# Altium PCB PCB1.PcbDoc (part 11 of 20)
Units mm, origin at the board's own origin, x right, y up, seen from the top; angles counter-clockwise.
Board outline 294.51 x 138.18 mm, 12 copper layers (Top Layer 1 _Signal, L2_GND, L3_Signals, L4_GND, L5_POWER, L6_Signals, L7_GND, L8_Signals, L9_GND, L10_POWER, L11_GND, Bottom Layer_Signals), stack 1.788 mm thick; 1254 components, 836 nets, 5699 pads, 2073 vias.
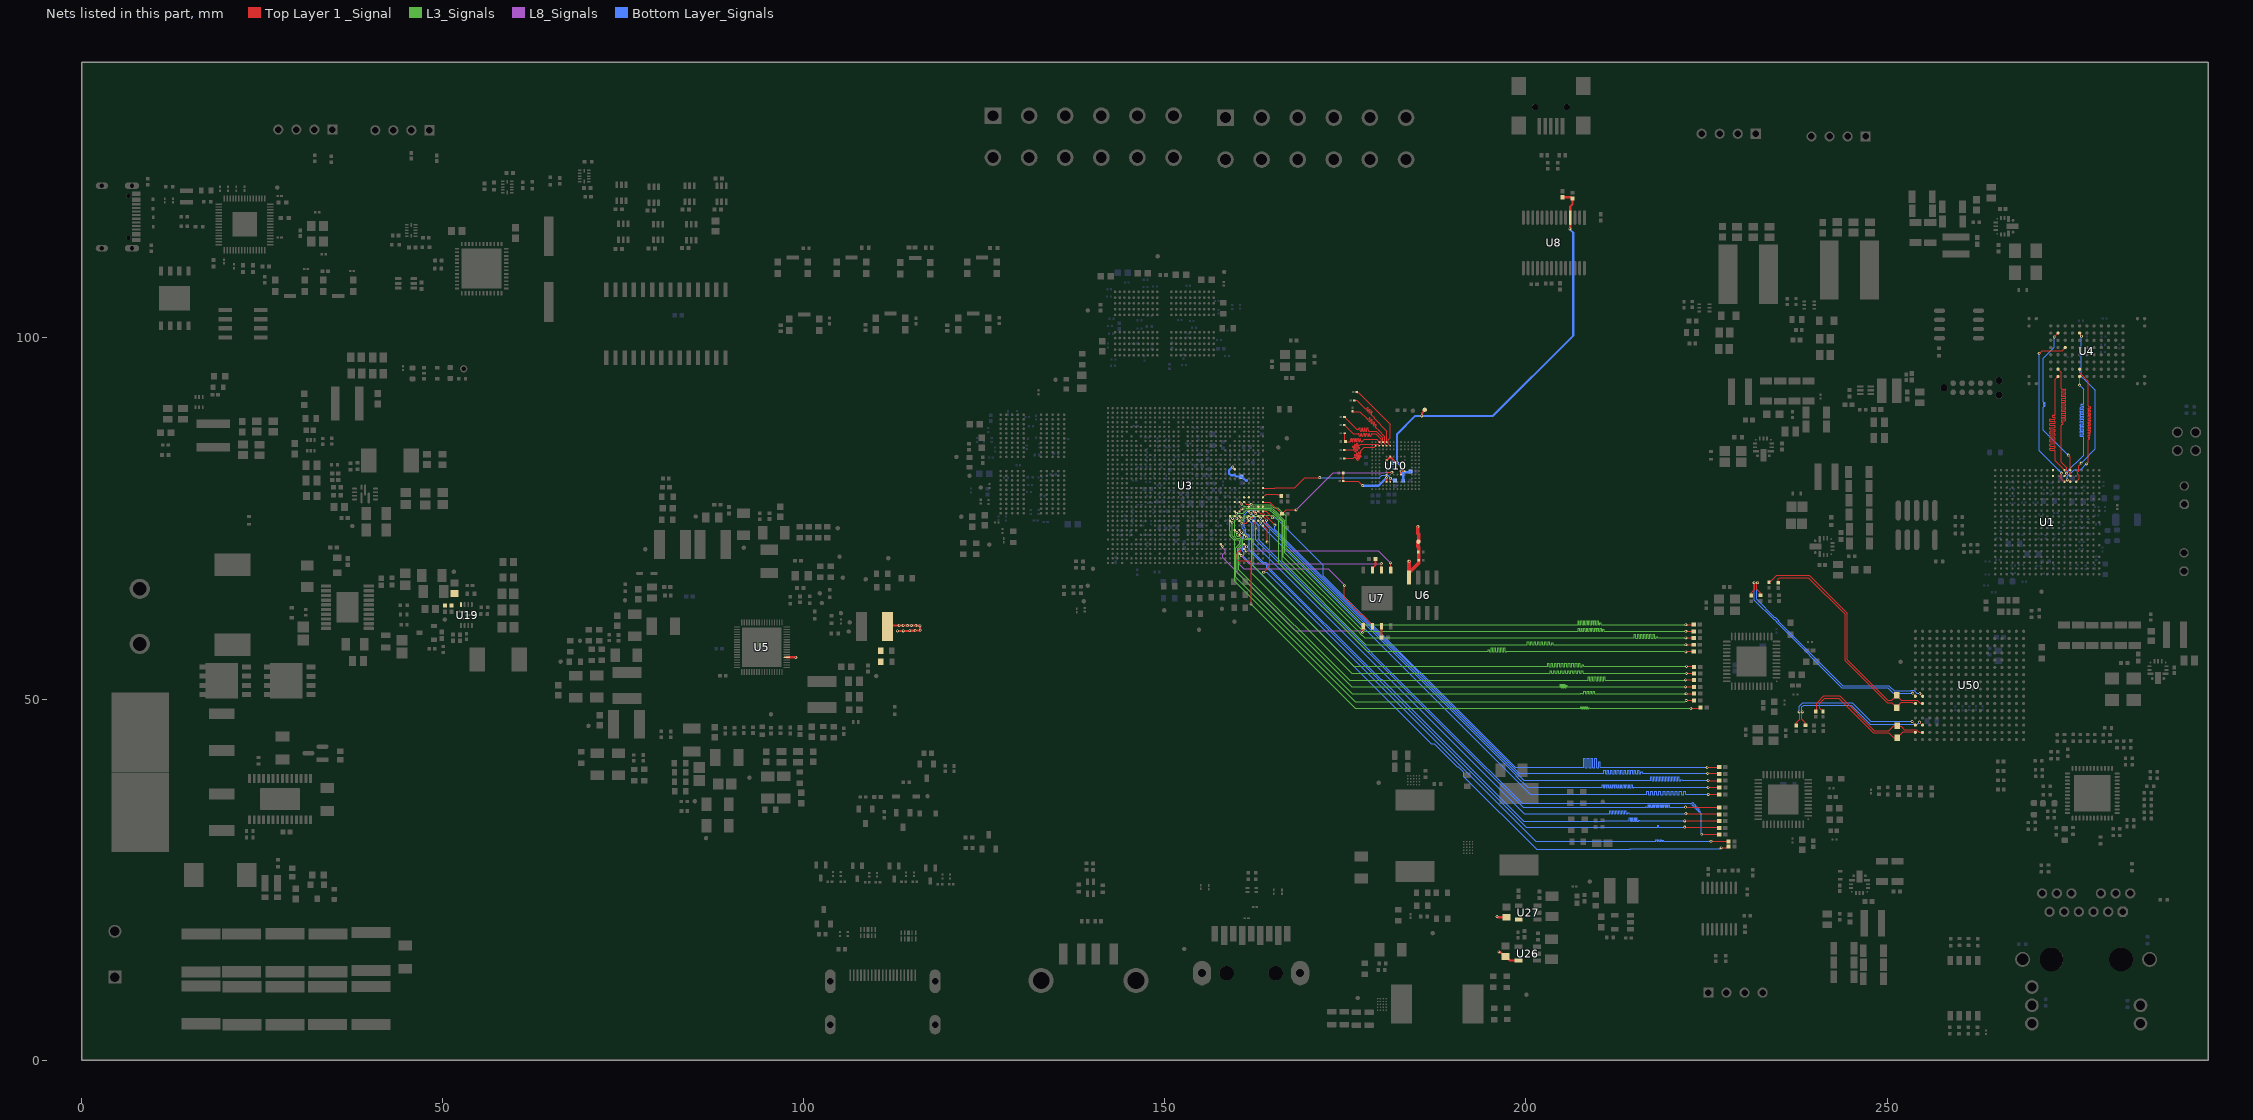
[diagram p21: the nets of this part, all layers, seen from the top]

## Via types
v1: diameter 0.4, hole 0.2, Top Layer 1 _Signal to Bottom Layer_Signals, 2009 vias
v2: diameter 0.508, hole 0.254, Top Layer 1 _Signal to Bottom Layer_Signals, 36 vias
v3: diameter 0.5, hole 0.2, Top Layer 1 _Signal to Bottom Layer_Signals, 12 vias
v4: diameter 1.27, hole 0.711, Top Layer 1 _Signal to Bottom Layer_Signals, 6 vias
v5: diameter 0.3, hole 0.2, Top Layer 1 _Signal to Bottom Layer_Signals, 5 vias
v6: diameter 0.254, hole 0.2, Top Layer 1 _Signal to Bottom Layer_Signals, 3 vias
v7: diameter 0.305, hole 0.2, Top Layer 1 _Signal to Bottom Layer_Signals, 1 vias
v8: diameter 0.254, hole 0.152, Top Layer 1 _Signal to Bottom Layer_Signals, 1 vias

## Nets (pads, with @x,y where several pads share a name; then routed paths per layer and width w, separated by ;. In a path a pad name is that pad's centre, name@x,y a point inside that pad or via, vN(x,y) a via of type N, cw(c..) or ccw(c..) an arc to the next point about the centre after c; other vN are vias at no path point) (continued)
EMMC.D2: U1.E3 U4.K3 | length 22.7
  Top Layer 1 _Signal w0.132: U1.E3@276.181,80.08 276.584,80.483 276.584,80.966 276.398,81.151 276.398,81.441 276.528,81.571 276.528,82.329 v1(276.867,82.668) ; U4.K3@276.672,100.669 276.672,100.583 276.925,100.329 v1(276.925,100.226)
  Bottom Layer_Signals w0.132: v1(276.867,82.668) 278.827,84.628 278.827,92.78 277.403,94.204 277.376,94.204 276.925,94.655 v1(276.925,100.226)
EMMC.D3: U1.F1 U4.N3 | length 22.2
  Top Layer 1 _Signal w0.132: v1(273.158,100.13) 273.158,100.155 U4.N3@273.672,100.669 ; v1(275.089,83.765) 275.343,83.511 275.343,81.718 U1.F1@275.381,81.68
  Bottom Layer_Signals w0.132: v1(273.158,100.13) 273.158,98.696 271.63,97.168 271.63,92.119 271.63,91.156 ccw(c271.762,91.156) 271.762,91.024 271.825,91.024 cw(c271.825,90.945) 271.825,90.867 271.683,90.867 ccw(c271.683,90.788) 271.683,90.709 271.825,90.709 cw(c271.825,90.631) 271.825,90.552 271.762,90.552 ccw(c271.762,90.42) 271.63,90.42 271.63,90.197 271.63,87.224 v1(275.089,83.765)
EMMC.D4: U1.F2 U4.N8 | length 26
  Top Layer 1 _Signal w0.132: U4.N8@273.672,95.669 274.122,95.218 274.122,93.123 274.122,93.058 ccw(c274.254,93.058) 274.254,92.926 274.646,92.926 cw(c274.646,92.796) 274.646,92.667 274.226,92.667 ccw(c274.226,92.537) 274.226,92.408 274.646,92.408 cw(c274.646,92.279) 274.646,92.149 274.226,92.149 ccw(c274.226,92.02) 274.226,91.89 274.646,91.89 cw(c274.646,91.761) 274.646,91.632 274.226,91.632 ccw(c274.226,91.502) 274.226,91.373 274.646,91.373 cw(c274.646,91.243) 274.646,91.114 274.226,91.114 ccw(c274.226,90.985) 274.226,90.855 274.646,90.855 cw(c274.646,90.726) 274.646,90.596 274.226,90.596 ccw(c274.226,90.467) 274.226,90.337 274.646,90.337 cw(c274.646,90.208) 274.646,90.079 274.226,90.079 ccw(c274.226,89.949) 274.226,89.82 274.646,89.82 cw(c274.646,89.69) 274.646,89.561 274.226,89.561 ccw(c274.226,89.432) 274.226,89.302 274.646,89.302 cw(c274.646,89.173) 274.646,89.043 274.226,89.043 ccw(c274.226,88.914) 274.226,88.785 274.617,88.785 cw(c274.617,88.655) 274.617,88.526 274.226,88.526 ccw(c274.226,88.396) 274.226,88.267 274.254,88.267 cw(c274.254,88.137) 274.254,88.008 ccw(c274.254,87.876) 274.122,87.876 274.122,87.563 274.122,82.786 274.917,81.991 274.917,81.699 275.373,81.243 275.373,80.888 U1.F2@275.381,80.88
EMMC.D5: U1.F3 U4.K8 | length 23.4
  Top Layer 1 _Signal w0.132: v1(274.955,80.34) 275.006,80.289 275.118,80.289 275.327,80.08 U1.F3@275.381,80.08 ; U4.K8@276.672,95.669 276.672,95.166 276.794,95.043 276.827,95.043 277.297,94.573 277.297,94.513 277.831,93.979 277.831,90.656 277.831,90.59 ccw(c277.963,90.59) 277.963,90.459 278.076,90.459 cw(c278.076,90.342) 278.076,90.225 277.923,90.225 ccw(c277.923,90.108) 277.923,89.992 278.076,89.992 cw(c278.076,89.875) 278.076,89.758 277.923,89.758 ccw(c277.923,89.642) 277.923,89.525 278.076,89.525 cw(c278.076,89.408) 278.076,89.291 277.923,89.291 ccw(c277.923,89.175) 277.923,89.058 278.076,89.058 cw(c278.076,88.941) 278.076,88.825 277.923,88.825 ccw(c277.923,88.708) 277.923,88.591 278.076,88.591 cw(c278.076,88.474) 278.076,88.358 277.923,88.358 ccw(c277.923,88.241) 277.923,88.124 278.076,88.124 cw(c278.076,88.008) 278.076,87.891 277.923,87.891 ccw(c277.923,87.774) 277.923,87.658 278.076,87.658 cw(c278.076,87.541) 278.076,87.424 277.923,87.424 ccw(c277.923,87.307) 277.923,87.191 278.076,87.191 cw(c278.076,87.074) 278.076,86.957 277.923,86.957 ccw(c277.923,86.841) 277.923,86.724 278.003,86.724 cw(c278.003,86.607) 278.003,86.49 277.923,86.49 ccw(c277.923,86.374) 277.923,86.257 277.963,86.257 cw(c277.963,86.14) 277.963,86.024 ccw(c277.963,85.892) 277.831,85.892 277.831,85.537 277.831,82.775 v1(277.61,82.554)
  Bottom Layer_Signals w0.132: v1(274.955,80.34) 274.985,80.371 274.985,80.828 275.928,81.77 276.827,81.77 v1(277.61,82.554)
EMMC.D6: U1.G1 U4.N9 | length 25.4
  Top Layer 1 _Signal w0.132: U4.N9@273.672,94.669 273.274,94.271 273.274,89.798 273.274,89.441 cw(c273.132,89.441) 273.132,89.299 273.015,89.299 ccw(c273.015,89.157) 273.015,89.015 273.158,89.015 cw(c273.158,88.872) 273.158,88.73 272.626,88.73 ccw(c272.626,88.588) 272.626,88.446 273.158,88.446 cw(c273.158,88.304) 273.158,88.162 272.626,88.162 ccw(c272.626,88.02) 272.626,87.878 273.158,87.878 cw(c273.158,87.736) 273.158,87.593 272.626,87.593 ccw(c272.626,87.451) 272.626,87.309 273.158,87.309 cw(c273.158,87.167) 273.158,87.025 272.626,87.025 ccw(c272.626,86.883) 272.626,86.741 273.158,86.741 cw(c273.158,86.599) 273.158,86.457 272.626,86.457 ccw(c272.626,86.314) 272.626,86.172 273.158,86.172 cw(c273.158,86.03) 273.158,85.888 272.626,85.888 ccw(c272.626,85.746) 272.626,85.604 273.158,85.604 cw(c273.158,85.462) 273.158,85.32 272.626,85.32 ccw(c272.626,85.177) 272.626,85.035 273.158,85.035 cw(c273.158,84.893) 273.158,84.751 272.626,84.751 ccw(c272.626,84.609) 272.626,84.467 273.132,84.467 cw(c273.132,84.325) 273.274,84.325 273.274,84.259 273.274,82.987 U1.G1@274.581,81.68
EMMC.D7: U1.G2 U4.K9 | length 23.6
  Top Layer 1 _Signal w0.132: U1.G2@274.581,80.88 274.865,81.164 v1(274.865,81.256) ; v1(276.663,93.461) 276.667,93.466 276.667,94.665 U4.K9@276.672,94.669
  Bottom Layer_Signals w0.132: v1(274.865,81.256) 274.916,81.308 274.916,81.47 277.216,83.77 277.216,86.174 277.216,86.239 ccw(c277.084,86.239) 277.084,86.371 276.816,86.371 cw(c276.816,86.488) 276.816,86.605 277.124,86.605 ccw(c277.124,86.721) 277.124,86.838 276.816,86.838 cw(c276.816,86.955) 276.816,87.072 277.124,87.072 ccw(c277.124,87.188) 277.124,87.305 276.816,87.305 cw(c276.816,87.422) 276.816,87.538 277.124,87.538 ccw(c277.124,87.655) 277.124,87.772 276.816,87.772 cw(c276.816,87.889) 276.816,88.005 277.124,88.005 ccw(c277.124,88.122) 277.124,88.239 276.816,88.239 cw(c276.816,88.355) 276.816,88.472 277.124,88.472 ccw(c277.124,88.589) 277.124,88.706 276.816,88.706 cw(c276.816,88.822) 276.816,88.939 277.124,88.939 ccw(c277.124,89.056) 277.124,89.172 276.816,89.172 cw(c276.816,89.289) 276.816,89.406 277.124,89.406 ccw(c277.124,89.523) 277.124,89.639 276.816,89.639 cw(c276.816,89.756) 276.816,89.873 277.124,89.873 ccw(c277.124,89.989) 277.124,90.106 276.816,90.106 cw(c276.816,90.223) 276.816,90.34 277.124,90.34 ccw(c277.124,90.456) 277.124,90.573 276.934,90.573 cw(c276.934,90.69) 276.934,90.806 277.084,90.806 ccw(c277.084,90.938) 277.216,90.938 277.216,91.818 277.216,92.909 v1(276.663,93.461)
EMMC.RSTn: U1.G3 U4.M5 | length 23.2
  Top Layer 1 _Signal w0.132: v1(271.06,97.818) 271.48,98.239 274.241,98.239 U4.M5@274.672,98.669 ; v1(274.162,81.282) 274.126,81.245 274.126,80.535 U1.G3@274.581,80.08
  Bottom Layer_Signals w0.132: v1(271.06,97.818) 271.06,84.384 v1(274.162,81.282)
EMMC_CLK: C217.2 U3.V34 U10.M6 | length 19.9
  Top Layer 1 _Signal w0.132: U3.V34@163.579,79.228 163.615,79.192 163.769,79.192 163.779,79.182 165.242,79.182 165.303,79.243 167.992,79.243 169.399,80.649 v1(171.44,80.649) ; U10.M6@181.204,80.07 181.214,80.08 181.214,80.555 v1(181.224,80.565)
  Bottom Layer_Signals w0.132: v1(171.44,80.649) 179.694,80.649 180.049,81.004 180.841,81.004 181.046,80.799 181.046,80.777 181.224,80.599 v1(181.224,80.565) ; v1@181.292,80.565 181.483,80.374 181.73,80.374 C217.2@181.87,80.235
eMMC_CMD: R60.1 R67.2 U10.M5 | length 8.4
  Top Layer 1 _Signal w0.132: R67.2@174.714,81.322 174.723,81.313 174.723,80.185 R60.1@174.731,80.176 176.767,80.176 v1(177.402,79.542)
  Top Layer 1 _Signal w0.305: v1(180.697,80.654) 180.697,80.629 180.704,80.623 U10.M5@180.704,80.07
  Bottom Layer_Signals w0.305: v1(177.402,79.542) 179.584,79.542 v1(180.697,80.654)
EMMC_D0: R56.1 R65.2 U10.A3 | length 9.6
  Top Layer 1 _Signal w0.132: R56.1@174.882,86.796 174.882,85.796 175.014,85.664 R65.2@175.014,85.639 175.531,85.639 175.597,85.639 ccw(c175.597,85.771) 175.728,85.771 175.728,85.99 cw(c175.807,85.99) 175.886,85.99 175.886,85.717 ccw(c175.964,85.717) 176.043,85.717 176.043,85.99 cw(c176.122,85.99) 176.2,85.99 176.2,85.717 ccw(c176.279,85.717) 176.357,85.717 176.357,85.99 cw(c176.436,85.99) 176.515,85.99 176.515,85.717 ccw(c176.593,85.717) 176.672,85.717 176.672,85.99 cw(c176.75,85.99) 176.829,85.99 176.829,85.717 ccw(c176.908,85.717) 176.986,85.717 176.986,85.906 cw(c177.065,85.906) 177.143,85.906 177.143,85.771 ccw(c177.275,85.771) 177.275,85.639 177.317,85.639 177.623,85.945 177.631,85.953 179.32,85.953 U10.A3@179.704,85.57
EMMC_D1: R57.1 U10.A4 | length 9.6
  Top Layer 1 _Signal w0.132: R57.1@174.876,89.049 174.922,89.049 176.534,87.437 176.6,87.371 176.607,87.364 ccw(c176.717,87.475) 176.864,87.423 cw(c176.955,87.423) 177.046,87.423 177.046,87.164 ccw(c177.138,87.164) 177.229,87.164 177.229,87.423 cw(c177.32,87.423) 177.412,87.423 177.412,87.164 ccw(c177.503,87.164) 177.594,87.164 177.594,87.423 cw(c177.686,87.423) 177.777,87.423 177.777,87.164 ccw(c177.868,87.164) 177.959,87.164 177.959,87.423 cw(c178.051,87.423) 178.142,87.423 178.142,87.23 ccw(c178.274,87.23) 178.274,87.098 178.663,87.098 179.253,87.098 180.204,86.147 U10.A4@180.204,85.57
EMMC_D2: R58.1 U10.A5 | length 9.7
  Top Layer 1 _Signal w0.132: R58.1@176.23,91.348 176.604,91.348 177.697,90.256 177.744,90.209 ccw(c177.837,90.302) 177.93,90.209 178.041,90.32 cw(c178.106,90.256) 178.17,90.32 cw(c178.106,90.256) 178.17,90.191 178.013,90.033 ccw(c178.077,89.969) 178.013,89.904 ccw(c178.077,89.969) 178.142,89.904 178.299,90.062 cw(c178.364,89.997) 178.429,90.062 cw(c178.364,89.997) 178.429,89.933 178.271,89.775 ccw(c178.336,89.711) 178.271,89.646 ccw(c178.336,89.711) 178.4,89.646 178.552,89.798 cw(c178.617,89.734) 178.682,89.798 cw(c178.617,89.734) 178.682,89.669 178.576,89.564 ccw(c178.669,89.47) 178.576,89.377 178.962,88.991 178.962,88.865 178.962,88.856 180.726,87.091 180.726,85.592 U10.A5@180.704,85.57
eMMC_D3: R59.1 U10.B2 | length 9.8
  Top Layer 1 _Signal w0.089: 178.421,84.836 178.97,84.836
  Top Layer 1 _Signal w0.132: R59.1@174.851,83.315 175.728,83.315 176.087,83.315 176.158,83.387 cw(c176.252,83.294) 176.345,83.387 176.642,83.09 ccw(c176.698,83.145) 176.753,83.09 ccw(c176.698,83.145) 176.753,83.201 176.247,83.707 cw(c176.303,83.762) 176.247,83.818 cw(c176.303,83.762) 176.359,83.818 176.865,83.312 ccw(c176.92,83.368) 176.976,83.312 ccw(c176.92,83.368) 176.976,83.423 176.519,83.88 cw(c176.575,83.935) 176.519,83.991 cw(c176.575,83.935) 176.63,83.991 177.087,83.534 ccw(c177.142,83.59) 177.198,83.534 ccw(c177.142,83.59) 177.198,83.646 176.777,84.067 cw(c176.832,84.122) 176.777,84.178 cw(c176.832,84.122) 176.888,84.178 177.012,84.054 ccw(c177.067,84.11) 177.123,84.054 ccw(c177.067,84.11) 177.123,84.165 cw(c177.216,84.259) 177.123,84.352 177.284,84.513 177.608,84.836 178.421,84.836 ; 178.97,84.836 U10.B2@179.204,85.07
eMMC_D4: R62.1 U10.B3 | length 9.8
  Top Layer 1 _Signal w0.089: 178.439,85.285 178.466,85.311 179.462,85.311
  Top Layer 1 _Signal w0.132: R62.1@174.849,84.489 175.46,84.489 176.093,84.489 cw(c176.093,84.357) 176.187,84.451 176.38,84.257 ccw(c176.436,84.313) 176.491,84.257 ccw(c176.436,84.313) 176.491,84.368 176.003,84.857 cw(c176.058,84.913) 176.003,84.968 cw(c176.058,84.913) 176.114,84.968 176.603,84.48 ccw(c176.658,84.535) 176.714,84.48 ccw(c176.658,84.535) 176.714,84.591 176.225,85.079 cw(c176.281,85.135) 176.225,85.191 cw(c176.281,85.135) 176.336,85.191 176.825,84.702 ccw(c176.88,84.757) 176.936,84.702 ccw(c176.88,84.757) 176.936,84.813 176.523,85.227 cw(c176.578,85.282) 176.523,85.338 cw(c176.578,85.282) 176.634,85.338 176.802,85.17 ccw(c176.895,85.263) 176.988,85.17 177.104,85.285 177.173,85.285 178.439,85.285 ; 179.462,85.311 U10.B3@179.704,85.07
eMMC_D5: R63.1 U10.B4 | length 9.6
  Top Layer 1 _Signal w0.089: 179.955,85.319 179.955,85.961
  Top Layer 1 _Signal w0.132: R63.1@174.87,87.923 174.916,87.923 176.109,86.729 176.546,86.729 176.795,86.729 cw(c176.795,86.597) 176.927,86.597 176.927,86.489 ccw(c177.018,86.489) 177.109,86.489 177.109,86.663 cw(c177.201,86.663) 177.292,86.663 177.292,86.489 ccw(c177.383,86.489) 177.475,86.489 177.475,86.663 cw(c177.566,86.663) 177.657,86.663 177.657,86.489 ccw(c177.749,86.489) 177.84,86.489 177.84,86.663 cw(c177.931,86.663) 178.023,86.663 178.023,86.489 ccw(c178.114,86.489) 178.205,86.489 178.205,86.663 cw(c178.296,86.663) 178.388,86.663 178.388,86.489 ccw(c178.479,86.489) 178.57,86.489 178.57,86.597 cw(c178.702,86.597) 178.702,86.729 179.187,86.729 179.263,86.653 179.955,85.961 ; 179.955,85.319 U10.B4@180.204,85.07
eMMC_D6: R61.1 U10.B5 | length 9.6
  Top Layer 1 _Signal w0.089: 180.445,85.329 180.445,86.336
  Top Layer 1 _Signal w0.132: R61.1@175.985,89.832 176.003,89.832 176.05,89.785 176.996,89.785 177.931,88.85 177.977,88.803 ccw(c178.071,88.896) 178.164,88.803 178.272,88.911 cw(c178.346,88.838) 178.419,88.911 cw(c178.346,88.838) 178.419,88.764 178.273,88.618 ccw(c178.347,88.545) 178.273,88.471 ccw(c178.347,88.545) 178.42,88.471 178.566,88.617 cw(c178.64,88.544) 178.713,88.617 cw(c178.64,88.544) 178.713,88.47 178.568,88.324 ccw(c178.641,88.251) 178.568,88.177 ccw(c178.641,88.251) 178.715,88.177 178.86,88.323 cw(c178.934,88.249) 179.008,88.323 cw(c178.934,88.249) 179.008,88.176 178.862,88.03 ccw(c178.935,87.956) 178.862,87.883 ccw(c178.935,87.956) 179.009,87.883 179.086,87.96 cw(c179.159,87.886) 179.233,87.96 cw(c179.159,87.886) 179.233,87.813 179.194,87.773 ccw(c179.287,87.68) 179.194,87.587 179.522,87.259 180.445,86.336 ; 180.445,85.329 U10.B5@180.704,85.07
eMMC_D7: R64.1 U10.B6 | length 9.7
  Top Layer 1 _Signal w0.089: 180.945,85.329 180.945,85.925
  Top Layer 1 _Signal w0.132: R64.1@176.578,92.5 176.644,92.434 176.815,92.434 181.222,88.027 181.222,86.202 180.945,85.925 ; 180.945,85.329 U10.B6@181.204,85.07
eMMC_DATA_STROBE: R68.2 U3.Y34 | length 2.8
  Top Layer 1 _Signal w0.132: U3.Y34@163.579,77.928 164.014,78.362 164.26,78.362 164.277,78.379 164.566,78.379 164.588,78.357 165.531,78.357 165.617,78.272 165.978,78.272 R68.2@166.13,78.119
eMMC_RSTn: R66.1 U3.AA34 U10.K5 | length 21.9
  Top Layer 1 _Signal w0.132: U3.AA34@163.579,77.278 164.554,77.278 R66.1@166.179,75.652 ; R66.1@166.223,75.652 R66.1@166.179,75.652 ; v1(168.186,76.182) 166.778,76.182 166.546,75.95 166.546,75.932 166.266,75.652 R66.1@166.179,75.652 ; U10.K5@180.704,81.07 181.016,81.382 181.409,81.382 v1(181.434,81.407) v1@181.423,81.419
  L8_Signals w0.089: v1(168.186,76.182) 173.305,81.302 180.382,81.302 180.487,81.407 v1(181.434,81.407)
EMMC_VCC: C23.1 C73.1 C74.1 C207.2 C208.2 C209.1 C520.2 C521.2 C543.1 C544.2 L10.1 R122.2 R301.2 R304.2 TP22.1 TP42.1 U3.P28 U5.5 U6.8 U8.4 U10.E6 U10.F5 U10.J10 U10.K9 U26.5 U27.5 | length 91.6
  Top Layer 1 _Signal w0.305: U5.5@97.644,55.77 v1(98.913,55.77) ; L10.1@111.572,60.058 111.698,60.184 v1(113.2,60.184) v1(113.753,60.184) 113.758,60.179 114.349,60.179 v1(114.354,60.175) 114.358,60.179 114.902,60.179 v1(114.907,60.184) 114.916,60.175 115.516,60.175 v1(115.526,60.165) 115.54,60.151 116.084,60.151 v1(116.098,60.137) 116.112,60.123 116.112,59.532 v1(116.126,59.518) 116.1,59.518 116.053,59.471 v1(115.423,59.471) 115.413,59.462 114.682,59.462 v1(114.672,59.453) 114.658,59.439 113.796,59.439 v1(113.782,59.425) 113.777,59.429 112.98,59.429 v1(112.975,59.434) ; v1(159.406,82.126) 159.406,82.119 159.419,82.106 159.419,82.092 159.679,81.832 U3.P28@159.679,81.828 U3.P28@159.675,81.828 ; U10.F5@180.704,83.07 180.714,83.07 181.204,83.559 U10.E6@181.204,83.57 181.342,83.431 181.342,83.42 182.028,82.735 v1(182.142,82.735) ; U10.K9@182.704,81.07 182.704,81.55 v1(182.717,81.563) 182.724,81.57 U10.J10@183.204,81.57 ; v1(185.578,89.206) 185.596,89.225 185.596,89.577 185.985,89.966 TP42.1@185.985,90.045 ; v1(195.988,19.884) 196.1,19.772 C521.2@197.29,19.772 ; v1(196.25,14.986) 196.268,14.968 196.457,14.968 197.082,14.343 C520.2@197.157,14.343 197.232,14.343 197.784,13.791 U26.5@198.953,13.791 ; C544.2@205.073,119.486 206.244,119.486 C543.1@206.43,119.3 206.43,118.485 206.141,118.196 U8.4@206.141,116.664 206.141,115.187 206.085,115.131 v1(206.085,115.105)
  Top Layer 1 _Signal w0.508: U6.8@183.795,66.832 U6.8@183.795,67.482 ; v1(183.83,69.081) 183.795,69.046 U6.8@183.795,67.482 ; v1(185.033,73.871) 185.038,73.867 185.038,72.942 185.055,72.924 185.055,72.899 185.177,72.778 185.177,71.881 185.111,71.815 TP22.1@185.111,71.79 ; TP22.1@185.055,71.79 185.055,71.107 185.157,71.006 R301.2@185.157,69.214 185.157,68.844 U6.8@183.795,67.482
  Bottom Layer_Signals w0.254: R122.2@160.557,80.827 160.557,80.802 160.911,80.449 160.959,80.449 161.153,80.254 161.348,80.254 C23.1@161.352,80.25
  Bottom Layer_Signals w0.305: v1(159.406,82.126) 159.38,82.126 159.217,81.962 159.174,81.962 158.918,81.706 158.918,81.644 158.881,81.607 158.881,81.236 159.138,80.979 159.712,80.979 159.864,80.827 160.557,80.827 R122.2@160.596,80.788 ; C207.2@181.506,82.761 v1@182.142,82.761 ; v1(182.142,82.735) v1@182.142,82.761 ; 182.874,81.38 183.012,81.241 183.012,80.309 183.019,80.302 C209.1@183.019,80.211 ; C208.2@184.028,81.494 183.94,81.406 182.9,81.406 182.742,81.563 v1(182.717,81.563) 182.717,82.255 182.21,82.761 v1@182.142,82.761 ; v1(206.085,115.105) 206.085,115.038 206.552,114.571 206.552,100.322 195.436,89.206 v1(185.578,89.206) 184.667,89.206 182.142,86.682 v1@182.142,82.761
EN_MP: C201.2 R81.1 R86.2 U19.12
FC1.RXD: U1.J1
FC1.TXD: U1.J2
FIBRI0_N: R228.1 R260.1 U50.T15 | length 17.5
  Top Layer 1 _Signal w0.161: R228.1@241.136,48.275 241.136,48.3 240.697,48.739 240.697,49.431 240.789,49.523 241.371,50.105 243.309,50.105 248.108,45.306 250.238,45.306 250.931,44.613 R260.1@251.412,44.613 252.247,45.448 253.687,45.448 253.703,45.432 253.866,45.432 U50.T15@253.919,45.379
FIBRI0_P: R229.1 R260.2 U50.R15 | length 18.9
  Top Layer 1 _Signal w0.161: R229.1@240.138,48.275 240.238,48.375 240.238,49.415 240.476,49.653 241.241,50.419 243.439,50.419 248.237,45.62 250.238,45.62 250.931,46.313 R260.2@251.412,46.313 251.492,46.232 251.94,46.232 252.411,45.762 254.077,45.762 254.459,45.38 U50.R15@254.919,45.379
FIBRI1_N: R249.1 R258.1 U50.T11 | length 31.3
  Top Layer 1 _Signal w0.161: R249.1@234.952,66.123 234.952,66.724 235.047,66.818 239.104,66.818 244.208,61.714 244.208,55.274 249.999,49.483 250.651,49.483 R258.1@251.344,48.79 251.424,48.87 251.424,48.991 251.969,49.535 253.464,49.535 253.62,49.379 U50.T11@253.919,49.379
FIBRI1_P: R251.1 R258.2 U50.R11 | length 33.4
  Top Layer 1 _Signal w0.161: R251.1@233.653,66.149 233.733,66.23 233.861,66.23 234.763,67.132 239.234,67.132 244.521,61.844 244.521,55.404 250.129,49.796 250.651,49.796 R258.2@251.344,50.49 251.424,50.409 251.424,50.394 251.969,49.849 254.151,49.849 254.62,49.379 U50.R11@254.919,49.379
FIBRO0_N: C596.1 U50.T14 | length 20.5
  Top Layer 1 _Signal w0.161: C596.1@237.429,46.35 237.429,46.69 237.91,47.171 237.91,48.129 v1(237.825,48.214) ; v1(253.463,46.887) 253.463,46.835 U50.T14@253.919,46.379
  Bottom Layer_Signals w0.161: v1(237.825,48.214) 237.825,48.986 238.318,49.479 245.176,49.479 247.767,46.887 v1(253.463,46.887)
FIBRO0_P: C595.1 U50.R14 | length 21
  Top Layer 1 _Signal w0.161: v1(238.309,48.214) 238.224,48.129 238.224,47.188 238.705,46.707 C595.1@238.705,46.366 ; v1(254.495,46.804) U50.R14@254.919,46.379
  Bottom Layer_Signals w0.161: v1(238.309,48.214) 238.223,48.3 238.223,48.94 238.448,49.165 245.046,49.165 247.688,46.523 254.15,46.523 254.431,46.804 v1(254.495,46.804)
FIBRO1_N: C610.1 U50.T10 | length 32.3
  Top Layer 1 _Signal w0.161: C610.1@231.188,64.349 231.188,64.69 231.671,65.173 231.671,66.018 v1(231.586,66.103) ; v1(253.534,50.823) 253.534,50.764 U50.T10@253.919,50.379
  Bottom Layer_Signals w0.161: v1(231.586,66.103) 231.62,66.069 231.62,63.681 234.28,61.02 234.384,61.02 234.703,60.701 234.703,60.597 243.752,51.549 250.116,51.549 250.841,50.823 v1(253.534,50.823)
FIBRO1_P: C609.1 U50.R10 | length 33
  Top Layer 1 _Signal w0.161: v1(232.07,66.103) 231.985,66.018 231.985,65.184 232.468,64.701 C609.1@232.468,64.36 ; v1(254.547,50.759) 254.547,50.751 U50.R10@254.919,50.379
  Bottom Layer_Signals w0.161: v1(232.07,66.103) 231.951,65.983 231.951,65.411 231.934,65.394 231.934,63.811 234.41,61.334 234.514,61.334 235.017,60.831 235.017,60.727 243.882,51.863 250.246,51.863 250.337,51.771 250.971,51.137 253.332,51.137 253.383,51.188 253.685,51.188 254.105,50.768 254.538,50.768 v1(254.547,50.759)
FSPI_CLK_M0: U3.AM29 U7.6 | length 21.2
  Top Layer 1 _Signal w0.132: U3.AM29@160.329,70.128 160.329,70.111 160.577,69.864 v1(160.577,69.846) ; v1(179.977,68.756) 179.993,68.74 179.993,67.873 U7.6@180.01,67.857
  L8_Signals w0.132: v1(160.577,69.846) 161.667,68.756 v1(179.977,68.756) v1@180.029,68.756
FSPI_CS0N_M0: U3.AK25 U7.1 | length 27
  Top Layer 1 _Signal w0.132: U3.AK25@157.729,71.428 157.729,71.394 157.749,71.394 158,71.143 v1(158,71.129) ; v1(177.389,59.191) 177.429,59.232 177.429,60.026 U7.1@177.47,60.067
  L8_Signals w0.132: v1(158,71.129) 158.039,71.091 158.039,70.869 158.116,70.792 158.188,70.792 158.393,70.587 158.393,70.297 158.188,70.092 158.078,70.092 158,70.015 158,69.544 160.834,66.711 168.099,59.445 177.08,59.445 177.334,59.191 v1(177.389,59.191)
FSPI_D0_M0: U3.AK30 U7.2 | length 27
  Top Layer 1 _Signal w0.132: U3.AK30@160.979,71.428 160.979,71.421 161.304,71.096 v1(161.304,71.089) ; v1(174.884,65.739) 174.832,65.688 174.832,65.466 174.815,65.448 174.815,64.083 177.154,61.744 177.312,61.744 178.74,60.317 U7.2@178.74,60.067
  L8_Signals w0.132: v1(161.304,71.089) 160.665,71.089 160.227,70.651 160.227,68.72 160.918,68.029 172.594,68.029 v1(174.884,65.739)
FSPI_D1_M0: U3.AL30 U7.5 | length 22.1
  Top Layer 1 _Signal w0.132: U3.AL30@160.979,70.778 160.979,70.774 161.241,70.512 v1(161.241,70.508) ; v1(181.221,68.841) 181.25,68.812 181.25,67.886 U7.5@181.28,67.857
  L8_Signals w0.132: v1(161.241,70.508) 179.521,70.508 181.188,68.841 v1(181.221,68.841)
FSPI_D2_M0: R72.1 U7.3 | length 1.6
  Top Layer 1 _Signal w0.254: R72.1@179.984,58.519 179.997,58.532 179.997,60.054 U7.3@180.01,60.067
FSPI_D3_M0: R73.1 U7.7 | length 1.7
  Top Layer 1 _Signal w0.254: U7.7@178.74,67.857 178.74,68.107 179.169,68.536 R73.1@179.169,69.357
GMAC0_MCLKINOUT: U3.AF34 | length 2.5
  Top Layer 1 _Signal w0.132: U3.AF34@163.579,74.028 164.145,73.462 164.145,71.75 v1(164.16,71.736)
GMAC0_MDC: U3.AB34
GMAC0_MDIO: U3.AB33
GMAC0_RSTn_L: U3.AB31
GMAC0_RXCLK: R222.1 U3.AE32 | length 89.5
  Top Layer 1 _Signal w0.132: U3.AE32@162.279,74.678 162.315,74.642 162.315,74.481 162.62,74.177 162.62,73.705 v1(162.622,73.703) ; v1(222.094,35.03) 226.71,35.03 R222.1@226.756,34.985
  Bottom Layer_Signals w0.132: v1(162.622,73.703) 162.596,73.676 162.596,72.082 199.647,35.03 216.038,35.03 216.594,35.03 216.594,35.08 216.751,35.08 216.751,35.005 216.908,35.005 216.908,35.359 217.066,35.359 217.066,35.005 217.223,35.005 217.223,35.359 217.38,35.359 217.38,35.005 217.537,35.005 217.537,35.359 217.695,35.359 217.695,35.005 217.852,35.005 217.852,35.359 218.009,35.359 218.009,35.005 218.166,35.005 218.166,35.359 218.324,35.359 218.324,35.005 218.481,35.005 218.481,35.359 218.638,35.359 218.638,35.005 218.795,35.005 218.795,35.359 218.952,35.359 218.952,35.005 219.11,35.005 219.11,35.359 219.267,35.359 219.267,35.005 219.424,35.005 219.424,35.359 219.581,35.359 219.581,35.005 219.739,35.005 219.739,35.359 219.896,35.359 219.896,35.005 220.053,35.005 220.053,35.03 220.119,35.03 v1(222.094,35.03)
GMAC0_RXD0: R224.1 U3.AD32 | length 89.5
  Top Layer 1 _Signal w0.132: v1(161.946,74.992) 161.946,74.993 162.279,75.327 U3.AD32@162.279,75.328 ; v1(222.147,34.125) 226.663,34.125 R224.1@226.752,34.035
  Bottom Layer_Signals w0.132: v1(161.946,74.992) 162.266,74.673 162.266,71.635 199.792,34.108 211.54,34.108 211.606,34.108 211.606,34.518 211.814,34.518 211.814,34.082 212.022,34.082 212.022,34.518 212.23,34.518 212.23,34.082 212.438,34.082 212.438,34.518 212.646,34.518 212.646,34.082 212.854,34.082 212.854,34.518 213.062,34.518 213.062,34.082 213.27,34.082 213.27,34.518 213.478,34.518 213.478,34.082 213.686,34.082 213.686,34.518 213.894,34.518 213.894,34.082 214.102,34.082 214.102,34.234 214.31,34.234 214.31,34.108 214.422,34.108 222.129,34.108 v1(222.147,34.125)
GMAC0_RXD1: R225.1 U3.AD31 | length 89.7
  Top Layer 1 _Signal w0.132: v1(161.357,75.058) 161.358,75.058 161.628,75.328 U3.AD31@161.629,75.328 ; v1(221.984,33.115) 226.736,33.115 R225.1@226.755,33.097
  Bottom Layer_Signals w0.132: v1(161.357,75.058) 162.05,74.365 162.05,70.533 163.639,68.944 163.984,68.944 164.315,68.612 164.315,68.268 179.875,52.708 180.051,52.708 199.71,33.049 210.777,33.049 210.844,33.115 214.27,33.115 214.336,33.115 214.336,33.572 214.493,33.572 214.493,33.09 214.65,33.09 214.65,33.572 214.807,33.572 214.807,33.09 214.965,33.09 214.965,33.572 215.122,33.572 215.122,33.09 215.279,33.09 215.279,33.572 215.436,33.572 215.436,33.09 215.594,33.09 215.594,33.206 215.751,33.206 215.751,33.115 215.965,33.115 v1(221.984,33.115)
GMAC0_RXD2: R226.1 U3.AC32 | length 89.7
  Top Layer 1 _Signal w0.132: U3.AC32@162.279,75.978 162.282,75.978 162.583,75.677 v1(162.585,75.677) ; v1(221.997,32.269) 226.639,32.269 R226.1@226.751,32.157
  Bottom Layer_Signals w0.132: v1(162.585,75.677) 162.585,76.092 162.508,76.169 161.622,76.169 160.999,75.546 160.999,73.773 161.231,73.542 161.231,72.959 161.654,72.536 161.654,70.624 163.55,68.728 163.894,68.728 164.099,68.523 164.099,68.178 200.014,32.264 215.68,32.264 218.095,32.264 218.095,32.25 218.252,32.25 218.252,32.508 218.409,32.508 218.409,32.239 218.566,32.239 218.566,32.264 218.632,32.264 221.992,32.264 v1(221.997,32.269)
GMAC0_RXD3: R227.1 U3.AC31 | length 89.5
  Top Layer 1 _Signal w0.132: U3.AC31@161.629,75.978 161.632,75.978 161.904,75.706 v1(161.907,75.706) ; v1(224.348,31.272) 226.716,31.272 R227.1@226.751,31.238
  Bottom Layer_Signals w0.132: v1(161.907,75.706) 162.493,75.119 162.493,74.571 163.041,74.023 163.041,71.992 194.25,40.782 194.25,40.753 195.097,39.907 195.125,39.907 199.458,35.575 222.777,35.575 222.839,35.513 222.886,35.466 223.092,35.672 223.221,35.543 222.997,35.319 223.126,35.19 223.35,35.414 223.48,35.285 223.255,35.061 223.384,34.932 223.609,35.156 223.738,35.027 223.514,34.802 223.643,34.673 223.867,34.898 223.996,34.768 223.772,34.544 223.901,34.415 223.991,34.505 224.12,34.375 224.048,34.304 224.257,34.095 224.257,33.99 224.257,31.436 224.348,31.345 v1(224.348,31.272)
GMAC0_RXDV_CRS: R223.1 U3.AE31 | length 90.5
  Top Layer 1 _Signal w0.132: v1@160.643,74.366 160.645,74.368 161.272,74.368 161.581,74.678 U3.AE31@161.629,74.678 ; v1(227.021,29.395) 227.871,29.395 R223.1@228.038,29.562
  Bottom Layer_Signals w0.132: v1(160.649,74.336) 160.686,74.298 160.686,73.66 161.015,73.331 161.015,72.675 160.775,72.435 160.775,70.48 160.926,70.328 160.926,69.857 160.941,69.842 160.941,69.672 167.661,62.952 167.723,62.952 186.886,43.789 187.29,43.789 190.473,40.607 190.66,40.607 191.41,39.857 191.41,39.265 201.468,29.207 214.414,29.207 214.447,29.239 226.81,29.239 226.966,29.395 v1(227.021,29.395)
GMAC0_TXCLK: R216.1 U3.AE33 | length 89.5
  Top Layer 1 _Signal w0.132: U3.AE33@162.929,74.678 162.929,74.675 163.228,74.376 v1(163.228,74.373) ; v1(225.24,36.787) 226.746,36.787 R216.1@226.766,36.767
  Bottom Layer_Signals w0.132: v1(163.228,74.373) 163.262,74.339 163.262,74.108 200.582,36.787 216.645,36.787 216.711,36.787 216.711,37.259 216.995,37.259 216.995,36.761 217.279,36.761 217.279,37.259 217.563,37.259 217.563,36.761 217.847,36.761 217.847,37.259 218.132,37.259 218.132,36.761 218.416,36.761 218.416,37.259 218.7,37.259 218.7,36.761 218.984,36.761 218.984,37.259 219.269,37.259 219.269,36.761 219.553,36.761 219.553,37.259 219.837,37.259 219.837,36.761 220.121,36.761 220.121,37.259 220.405,37.259 220.405,36.761 220.69,36.761 220.69,37.259 220.974,37.259 220.974,36.761 221.258,36.761 221.258,37.259 221.542,37.259 221.542,36.761 221.827,36.761 221.827,37.223 222.111,37.223 222.111,36.787 222.316,36.787 v1(225.24,36.787)
GMAC0_TXD0: R218.1 U3.AD33 | length 89.5
  Top Layer 1 _Signal w0.132: U3.AD33@162.929,75.328 162.94,75.328 163.22,75.048 v1(163.231,75.048) ; v1(225.233,37.752) 226.753,37.752 R218.1@226.773,37.732
  Bottom Layer_Signals w0.132: v1(163.231,75.048) 163.282,74.997 163.282,74.8 163.359,74.723 163.373,74.723 198.665,39.431 198.665,39.323 200.236,37.752 210.491,37.752 210.557,37.752 210.557,38.14 210.74,38.14 210.74,37.727 210.923,37.727 210.923,38.14 211.105,38.14 211.105,37.727 211.288,37.727 211.288,38.14 211.47,38.14 211.47,37.727 211.653,37.727 211.653,38.14 211.836,38.14 211.836,37.727 212.018,37.727 212.018,38.14 212.201,38.14 212.201,37.727 212.384,37.727 212.384,38.14 212.566,38.14 212.566,37.727 212.749,37.727 212.749,38.14 212.931,38.14 212.931,37.727 213.114,37.727 213.114,38.14 213.297,38.14 213.297,37.727 213.479,37.727 213.479,38.14 213.662,38.14 213.662,37.727 213.845,37.727 213.845,38.14 214.027,38.14 214.027,37.727 214.21,37.727 214.21,38.14 214.392,38.14 214.392,37.727 214.575,37.727 214.575,38.14 214.758,38.14 214.758,37.727 214.94,37.727 214.94,37.752 215.107,37.752 v1(225.233,37.752)
GMAC0_TXD1: R219.1 U3.AD34 | length 89.7
  Top Layer 1 _Signal w0.132: U3.AD34@163.579,75.328 163.579,75.284 164.075,74.789 v1(164.075,74.745) ; v1(225.22,38.741) 225.269,38.692 R219.1@226.77,38.692
  Bottom Layer_Signals w0.132: v1(164.075,74.745) 164.096,74.724 164.096,74.347 199.702,38.741 217.235,38.741 217.301,38.741 217.301,39.256 217.509,39.256 217.509,38.707 217.717,38.707 217.717,39.256 217.925,39.256 217.925,38.707 218.133,38.707 218.133,39.256 218.341,39.256 218.341,38.707 218.549,38.707 218.549,39.256 218.757,39.256 218.757,38.707 218.965,38.707 218.965,39.256 219.173,39.256 219.173,38.707 219.381,38.707 219.381,39.256 219.589,39.256 219.589,38.707 219.797,38.707 219.797,39.256 220.005,39.256 220.005,38.707 220.213,38.707 220.213,39.256 220.421,39.256 220.421,38.707 220.629,38.707 220.629,39.256 220.837,39.256 220.837,38.707 221.045,38.707 221.045,39.256 221.253,39.256 221.253,38.707 221.461,38.707 221.461,38.795 221.669,38.795 221.669,38.741 221.909,38.741 v1(225.22,38.741)
GMAC0_TXD2: R187.1 U3.AC33 | length 89.9
  Top Layer 1 _Signal w0.132: U3.AC33@162.929,75.978 163.27,75.638 163.708,75.638 165.246,74.099 v1(165.246,74.084) ; v1(225.159,39.708) 226.684,39.708 R187.1@226.769,39.622
  Bottom Layer_Signals w0.132: v1(165.246,74.084) 165.246,73.502 199.04,39.708 210.729,39.708 210.794,39.708 210.794,40.147 211.028,40.147 211.028,39.682 211.261,39.682 211.261,40.147 211.495,40.147 211.495,39.682 211.728,39.682 211.728,40.147 211.962,40.147 211.962,39.682 212.195,39.682 212.195,40.147 212.428,40.147 212.428,39.682 212.662,39.682 212.662,40.147 212.895,40.147 212.895,39.682 213.129,39.682 213.129,40.147 213.362,40.147 213.362,39.682 213.596,39.682 213.596,40.147 213.829,40.147 213.829,39.682 214.062,39.682 214.062,40.147 214.296,40.147 214.296,39.682 214.529,39.682 214.529,40.147 214.763,40.147 214.763,39.682 214.996,39.682 214.996,40.147 215.23,40.147 215.23,39.682 215.463,39.682 215.463,40.147 215.696,40.147 215.696,39.682 215.93,39.682 215.93,39.904 216.163,39.904 216.163,39.708 219.486,39.708 v1(225.159,39.708)
GMAC0_TXD3: R221.1 U3.AC34 | length 90.4
  Top Layer 1 _Signal w0.132: U3.AC34@163.579,75.978 164.026,75.978 v1(164.898,75.106) ; v1(225.089,40.538) 226.736,40.538 R221.1@226.768,40.57
  Bottom Layer_Signals w0.132: v1(164.898,75.106) 165.342,75.106 165.503,74.945 165.554,74.945 165.759,74.74 165.759,74.689 171.959,68.489 171.959,67.094 198.515,40.538 207.912,40.538 207.978,40.538 207.978,41.768 208.237,41.768 208.237,40.513 208.496,40.513 208.496,41.768 208.755,41.768 208.755,40.513 209.014,40.513 209.014,41.768 209.272,41.768 209.272,40.513 209.531,40.513 209.531,41.768 209.79,41.768 209.79,40.513 210.049,40.513 210.049,41.331 210.308,41.331 210.308,40.538 213.061,40.538 v1(225.089,40.538)
GMAC0_TXEN: R217.1 U3.AE34 | length 89.5
  Top Layer 1 _Signal w0.132: U3.AE34@163.579,74.678 164.554,73.703 164.554,68.438 v1(163.676,67.561) ; v1(225.628,30.302) 227.983,30.302 R217.1@228.039,30.246
  Bottom Layer_Signals w0.132: v1(163.676,67.561) 164.102,67.561 201.361,30.302 217.94,30.302 218.006,30.302 218.006,30.525 218.164,30.525 218.164,30.277 218.321,30.277 218.321,30.525 218.478,30.525 218.478,30.277 218.635,30.277 218.635,30.525 218.793,30.525 218.793,30.277 218.95,30.277 218.95,30.462 219.107,30.462 219.107,30.302 222.098,30.302 v1(225.628,30.302)
GMAC1_MCLKINOUT: U3.AE29
GMAC1_MDC: U3.Y31
GMAC1_MDIO: U3.Y30
GMAC1_RSTn_L: U3.AA28
GMAC1_RXCLK: R240.1 U3.AH30 | length 81.7
  Top Layer 1 _Signal w0.132: U3.AH30@160.979,72.728 160.979,72.722 161.265,72.436 v1(161.265,72.43) ; v1(222.232,54.515) 223.216,54.515 R240.1@223.271,54.46
  L3_Signals w0.113: v1(161.265,72.43) 161.343,72.43 161.487,72.286 161.609,72.286 161.972,72.286 162.207,72.051 162.207,71.688 162.207,68.455 176.146,54.515 202.944,54.515 203,54.515 203,54.953 203.24,54.953 203.24,54.49 203.479,54.49 203.479,54.953 203.719,54.953 203.719,54.49 203.958,54.49 203.958,54.953 204.198,54.953 204.198,54.49 204.437,54.49 204.437,54.953 204.677,54.953 204.677,54.49 204.917,54.49 204.917,54.953 205.156,54.953 205.156,54.49 205.396,54.49 205.396,54.953 205.635,54.953 205.635,54.49 205.875,54.49 205.875,54.953 206.114,54.953 206.114,54.49 206.354,54.49 206.354,54.953 206.593,54.953 206.593,54.49 206.833,54.49 206.833,54.953 207.072,54.953 207.072,54.49 207.312,54.49 207.312,54.953 207.551,54.953 207.551,54.49 207.791,54.49 207.791,54.77 208.03,54.77 208.03,54.515 208.884,54.515 v1(222.232,54.515)
GMAC1_RXD0: R243.1 U3.AG29 | length 81.9
  Top Layer 1 _Signal w0.132: U3.AG29@160.329,73.378 160.329,73.367 160.615,73.081 v1(160.615,73.071) ; v1(222.206,53.559) R243.1@223.27,53.558 R243.1@223.27,53.558
  L3_Signals w0.113: v1(160.615,73.071) 160.615,73.069 160.875,72.809 160.875,72.729 160.925,72.68 160.925,72.289 161.124,72.09 161.891,72.09 162.011,71.97 162.011,67.431 175.882,53.559 202.537,53.559 203.12,53.559 ; 203.12,53.559 203.36,53.559 203.36,53.924 203.599,53.924 203.599,53.534 203.839,53.534 203.839,53.924 204.078,53.924 204.078,53.534 204.318,53.534 204.318,53.924 204.557,53.924 204.557,53.534 204.797,53.534 204.797,53.924 205.036,53.924 205.036,53.534 205.276,53.534 205.276,53.924 205.515,53.924 205.515,53.534 205.755,53.534 205.755,53.924 205.994,53.924 205.994,53.534 206.234,53.534 206.234,53.924 206.473,53.924 206.473,53.534 206.713,53.534 206.713,53.924 206.952,53.924 206.952,53.534 207.192,53.534 207.192,53.924 207.431,53.924 207.431,53.534 207.671,53.534 207.671,53.924 207.91,53.924 207.91,53.534 208.15,53.534 208.15,53.559 208.206,53.559 v1(222.206,53.559)
GMAC1_RXD1: R244.1 U3.AG28 | length 82
  Top Layer 1 _Signal w0.132: U3.AG28@159.679,73.378 159.679,73.373 159.987,73.065 v1(159.987,73.059) ; v1(222.1,52.639) 223.237,52.639 R244.1@223.261,52.616
  L3_Signals w0.113: v1(159.987,73.059) 159.987,72.596 160.053,72.53 160.278,72.53 160.788,72.02 160.788,71.304 160.308,70.824 160.308,70.059 160.237,69.987 160.237,67.916 175.58,52.573 205.016,52.573 208.492,52.573 208.577,52.573 208.633,52.573 208.633,53.082 208.848,53.082 208.848,52.548 209.062,52.548 209.062,53.082 209.276,53.082 209.276,52.548 209.49,52.548 209.49,53.082 209.704,53.082 209.704,52.548 209.918,52.548 209.918,53.082 210.132,53.082 210.132,52.548 210.346,52.548 210.346,53.082 210.561,53.082 210.561,52.548 210.775,52.548 210.775,53.066 210.989,53.066 210.989,52.573 211.367,52.573 221.89,52.573 221.902,52.584 222.045,52.584 v1(222.1,52.639)
GMAC1_RXD2: R245.1 U3.AD27 | length 82.1
  Top Layer 1 _Signal w0.132: U3.AD27@159.029,75.328 159.038,75.328 159.356,75.01 v1(159.365,75.01) ; v1(222.084,51.685) 222.093,51.676 R245.1@223.264,51.676
  L3_Signals w0.113: v1(159.365,75.01) 159.647,74.728 159.647,72.517 159.912,72.253 160.16,72.253 160.277,72.253 160.591,71.938 160.591,71.733 160.591,71.385 160.112,70.906 160.112,70.14 160.04,70.069 160.04,67.504 175.86,51.685 204.709,51.685 204.765,51.685 204.765,52.025 204.903,52.025 204.903,51.527 205.041,51.527 205.041,52.025 205.179,52.025 205.179,51.527 205.317,51.527 205.317,52.025 205.455,52.025 205.455,51.527 205.593,51.527 205.593,51.874 205.731,51.874 205.731,51.685 208.727,51.685 v1(222.084,51.685)
GMAC1_RXD3: R246.1 U3.AE27 | length 82
  Top Layer 1 _Signal w0.132: U3.AE27@159.029,74.678 159.045,74.678 159.292,74.431 v1(159.307,74.431) ; v1(222.181,50.737) R246.1@223.264,50.737
  L3_Signals w0.113: v1(159.307,74.431) 159.307,72.579 159.83,72.056 159.99,72.056 160.196,72.056 160.395,71.857 160.395,71.651 160.395,71.466 159.844,70.915 159.844,66.835 175.942,50.737 207.321,50.737 207.609,50.737 207.609,50.821 207.824,50.821 207.824,50.711 208.038,50.711 208.038,51.069 208.252,51.069 208.252,50.711 208.466,50.711 208.466,51.069 208.68,51.069 208.68,50.711 208.894,50.711 208.894,51.069 209.108,51.069 209.108,50.711 209.322,50.711 209.322,51.069 209.536,51.069 209.536,50.711 209.751,50.711 209.751,50.737 209.807,50.737 v1(222.181,50.737)
GMAC1_RXDV_CRS: R241.1 U3.AH29 | length 82.5
  Top Layer 1 _Signal w0.132: U3.AH29@160.329,72.728 160.639,72.418 160.639,70.65 160.442,70.453 160.216,70.453 160.02,70.256 160.02,69.35 160.223,69.147 161.749,69.147 161.952,68.944 161.952,63.195 v1(161.925,63.168) ; v1(222.844,48.699) 224.061,48.699 R241.1@224.18,48.819
  L3_Signals w0.113: v1@161.937,63.143 176.381,48.699 207.532,48.699 207.588,48.699 207.588,48.944 207.726,48.944 207.726,48.674 207.864,48.674 207.864,48.944 208.002,48.944 208.002,48.674 208.14,48.674 208.14,48.944 208.278,48.944 208.278,48.674 208.416,48.674 208.416,48.944 208.554,48.944 208.554,48.674 208.692,48.674 208.692,48.819 208.83,48.819 208.83,48.699 210.578,48.699 v1(222.844,48.699)
GMAC1_TXCLK: R189.1 U3.AD28 | length 81.5
  Top Layer 1 _Signal w0.132: U3.AD28@159.679,75.328 159.679,75.316 159.974,75.021 v1(159.974,75.01) ; v1(222.145,56.536) 222.193,56.584 223.235,56.584 R189.1@223.246,56.596
  L3_Signals w0.113: v1(159.974,75.01) 159.974,74.932 160.081,74.825 160.081,74.821 160.196,74.707 160.717,74.707 161.017,75.007 161.017,75.271 161.144,75.398 161.733,75.398 161.795,75.337 163.039,75.337 163.149,75.446 165.039,75.446 165.238,75.247 165.803,74.682 165.803,68.83 178.05,56.584 192.779,56.584 194.778,56.584 194.778,56.821 194.993,56.821 194.993,56.559 195.207,56.559 195.207,57.085 195.421,57.085 195.421,56.559 195.635,56.559 195.635,57.085 195.849,57.085 195.849,56.559 196.063,56.559 196.063,57.085 196.277,57.085 196.277,56.559 196.491,56.559 196.491,57.085 196.706,57.085 196.706,56.559 196.92,56.559 196.92,57.085 197.134,57.085 197.134,56.559 197.348,56.559 197.348,56.584 197.404,56.584 222.097,56.584 v1(222.145,56.536)
GMAC1_TXD0: R236.1 U3.AC28 | length 81.4
  Top Layer 1 _Signal w0.132: U3.AC28@159.679,75.978 159.679,75.966 159.907,75.738 v1(159.907,75.726) ; v1(222.14,57.517) 223.236,57.517 R236.1@223.238,57.514
  L3_Signals w0.113: v1(159.907,75.726) 160.839,75.726 161.346,76.234 164.462,76.234 165.053,75.643 165.12,75.643 166.225,74.538 166.225,69.113 177.821,57.517 200.132,57.517 200.188,57.517 200.188,57.927 200.428,57.927 200.428,57.492 200.667,57.492 200.667,57.927 200.907,57.927 200.907,57.492 201.146,57.492 201.146,57.927 201.386,57.927 201.386,57.492 201.625,57.492 201.625,57.927 201.865,57.927 201.865,57.492 202.104,57.492 202.104,57.927 202.344,57.927 202.344,57.492 202.583,57.492 202.583,57.927 202.823,57.927 202.823,57.492 203.062,57.492 203.062,57.927 203.302,57.927 203.302,57.492 203.541,57.492 203.541,57.787 203.781,57.787 203.781,57.517 204.402,57.517 v1(222.14,57.517)
GMAC1_TXD1: R237.1 U3.AC29 | length 81.5
  Top Layer 1 _Signal w0.132: U3.AC29@160.329,75.978 U3.AC29@160.329,75.978 160.663,76.314 v1(160.663,76.316) ; v1(222.145,58.464) 223.221,58.464 R237.1@223.242,58.443
  L3_Signals w0.113: v1(160.663,76.316) 161.15,76.316 161.265,76.43 164.544,76.43 165.135,75.839 165.201,75.839 166.421,74.619 166.421,69.73 177.048,59.103 177.048,59.05 177.248,58.851 177.3,58.851 177.687,58.464 207.36,58.464 214.967,58.464 215.024,58.464 215.024,58.988 215.238,58.988 215.238,58.439 215.452,58.439 215.452,58.988 215.666,58.988 215.666,58.439 215.88,58.439 215.88,58.988 216.094,58.988 216.094,58.439 216.308,58.439 216.308,58.988 216.522,58.988 216.522,58.439 216.737,58.439 216.737,58.988 216.951,58.988 216.951,58.439 217.165,58.439 217.165,58.988 217.379,58.988 217.379,58.439 217.593,58.439 217.593,58.988 217.807,58.988 217.807,58.439 218.021,58.439 218.021,58.625 218.235,58.625 218.235,58.464 219.407,58.464 v1(222.145,58.464)
GMAC1_TXD2: R238.1 U3.AA29 | length 81.7
  Top Layer 1 _Signal w0.132: U3.AA29@160.329,77.278 160.329,77.27 160.59,77.009 v1(160.59,77) ; v1(222.15,59.382) 223.228,59.382 R238.1@223.241,59.369
  L3_Signals w0.113: v1(160.59,77) 160.93,76.661 161.139,76.661 161.173,76.626 164.625,76.626 165.216,76.035 165.283,76.035 166.617,74.701 166.617,70.224 177.31,59.531 177.529,59.531 177.679,59.382 207.202,59.382 207.259,59.382 207.259,59.809 207.447,59.809 207.447,59.357 207.636,59.357 207.636,59.809 207.825,59.809 207.825,59.357 208.013,59.357 208.013,59.809 208.202,59.809 208.202,59.357 208.391,59.357 208.391,59.809 208.58,59.809 208.58,59.357 208.768,59.357 208.768,59.809 208.957,59.809 208.957,59.357 209.146,59.357 209.146,59.809 209.335,59.809 209.335,59.357 209.523,59.357 209.523,59.809 209.712,59.809 209.712,59.357 209.901,59.357 209.901,59.809 210.089,59.809 210.089,59.357 210.278,59.357 210.278,59.809 210.467,59.809 210.467,59.357 210.656,59.357 210.656,59.661 210.844,59.661 210.844,59.382 211.321,59.382 v1(222.15,59.382)
GMAC1_TXD3: R239.1 U3.AA30 | length 81.8
  Top Layer 1 _Signal w0.132: U3.AA30@160.979,77.278 161.291,76.966 v1(161.954,76.966) ; v1(222.143,60.286) 223.212,60.286 R239.1@223.233,60.307
  L3_Signals w0.113: v1(161.954,76.966) 162.008,76.913 164.616,76.913 165.078,76.451 165.637,76.451 166.814,75.275 166.814,70.876 177.403,60.286 207.16,60.286 207.216,60.286 207.216,60.847 207.405,60.847 207.405,60.26 207.593,60.26 207.593,60.847 207.782,60.847 207.782,60.26 207.971,60.26 207.971,60.847 208.16,60.847 208.16,60.26 208.348,60.26 208.348,60.847 208.537,60.847 208.537,60.26 208.726,60.26 208.726,60.847 208.915,60.847 208.915,60.26 209.103,60.26 209.103,60.847 209.292,60.847 209.292,60.26 209.481,60.26 209.481,60.847 209.669,60.847 209.669,60.26 209.858,60.26 209.858,60.847 210.047,60.847 210.047,60.26 210.236,60.26 210.236,60.574 210.424,60.574 210.424,60.286 210.515,60.286 v1(222.143,60.286)
GMAC1_TXEN: R220.1 U3.AD29 | length 82
  Top Layer 1 _Signal w0.132: U3.AD29@160.329,75.328 160.329,75.311 160.576,75.064 v1(160.576,75.047) ; v1(222.193,49.795) 223.267,49.795 R220.1@223.274,49.789
  L3_Signals w0.113: v1(160.576,75.047) 160.24,75.384 159.257,75.384 158.967,75.094 158.967,73.297 159.046,73.218 159.046,72.563 159.688,71.921 159.688,71.038 159.648,70.997 159.648,66.277 176.331,49.593 221.984,49.593 222.185,49.795 v1(222.193,49.795)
